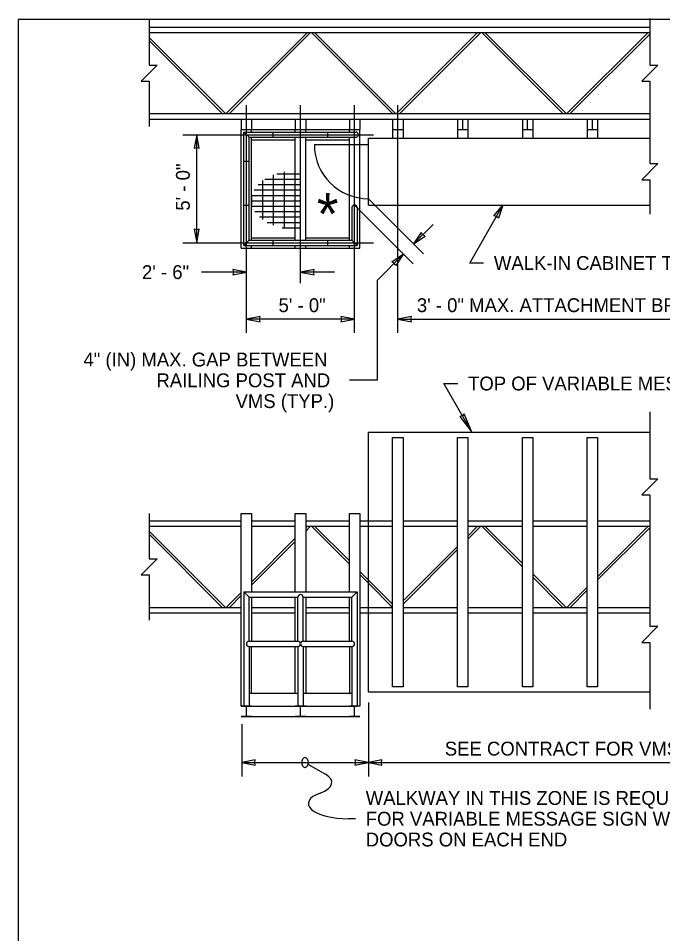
# Model space of a CAD drawing. Extents: x 99862 to 103151, y 100000 to 105076.
# Drawn here: x 99862 to 100607, y 101019 to 102077 of the extents above; entities that cross this region are included whole.
import ezdxf

# ---------------------------------------------------------------- set-up
doc = ezdxf.new("R2010")
doc.units = 0
for name, color, linetype in [('Level 1', 7, 'Continuous'), ('Level 14', 7, 'Continuous'), ('Level 15', 7, 'Continuous'), ('Level 18', 7, 'Continuous'), ('Level 2', 7, 'Continuous'), ('Level 20', 7, 'Continuous'), ('Level 22', 7, 'Continuous'), ('Level 23', 7, 'Continuous'), ('Level 26', 7, 'Continuous'), ('Level 27', 7, 'Continuous'), ('Level 7', 7, 'Continuous')]:
    doc.layers.add(name, color=color, linetype=linetype)

msp = doc.modelspace()

# ---------------------------------------------------------------- linework, layer by layer
at = {"layer": 'Level 1'}
msp.add_lwpolyline([(99862, 99999.5), (103151, 99999.5), (103151, 102075.5), (99862, 102075.5)], close=True, dxfattribs=at)
at = {"layer": 'Level 14'}
msp.add_line((100251.7, 101152), (100243.7, 101152), dxfattribs=at)
for centre, start_param, end_param in [((100178.1, 101194), 5.497747, 6.859209), ((100243.7, 101169.4), 2.356226, 4.712389)]:
    msp.add_ellipse(centre, major_axis=(46.4, 0), ratio=0.375, start_param=start_param, end_param=end_param, dxfattribs=at)
at = {"layer": 'Level 15'}
for p, q in [((100125.8, 101713.3), (100125.8, 101976.3)), ((100188.3, 101770.8), (100188.3, 101976.3)), ((100250.8, 101713.3), (100250.8, 101976.3)), ((100300.8, 101713.3), (100300.8, 101976.3)), ((100052.3, 101942.3), (100272.8, 101942.3)), ((100068.3, 101817.4), (100068.3, 101942.3)), ((100250.8, 101861), (100318.6, 101793.1)), ((100266.8, 101868.3), (100330.3, 101804.8)), ((100383.9, 101794), (100422.4, 101860.8)), ((100341.6, 101838.7), (100319, 101816.1)), ((100052.3, 101817.4), (100272.8, 101817.4)), ((100307.3, 101804.5), (100276.8, 101773.9)), ((100399.9, 101794), (100383.9, 101794)), ((100125.8, 101783.5), (100073.7, 101783.5)), ((100227.7, 101783.5), (100188.3, 101783.5)), ((100276.8, 101773.9), (100276.8, 101658.5)), ((100250.8, 101729.3), (100125.8, 101729.3)), ((100300.8, 101729.3), (100832, 101729.3)), ((100276.8, 101658.5), (100244.8, 101658.5)), ((100386.5, 101598.5), (100354, 101654.8)), ((100354, 101654.8), (100370, 101654.8)), ((100266.8, 101286.2), (100266.8, 101201)), ((100120.3, 101261.4), (100120.3, 101201)), ((100120.3, 101217), (100266.8, 101217)), ((100266.8, 101217), (100866.3, 101217)), ((100196.8, 101215.1), (100217, 101203.5))]:
    msp.add_line(p, q, dxfattribs=at)
for points in [[(100013.3, 102075), (100013.3, 102022.7), (100022.5, 102022.7), (100004, 102004.2), (100013.3, 102004.2), (100013.3, 101951.9)], [(100592.1, 102076.7), (100592.1, 102022.7), (100601.3, 102022.7), (100582.8, 102004.2), (100592.1, 102004.2), (100592.1, 101951.9)], [(100592.1, 101961.1), (100592.1, 101908.9), (100601.3, 101908.9), (100582.8, 101890.3), (100592.1, 101890.3), (100592.1, 101850.3)], [(100592.1, 101622.1), (100592.1, 101544.8), (100601.3, 101544.8), (100582.8, 101526.3), (100592.1, 101526.3), (100592.1, 101374.4), (100601.3, 101374.4), (100582.8, 101355.8), (100592.1, 101355.8), (100592.1, 101278.6)], [(100013.3, 101504.6), (100013.3, 101452.3), (100022.5, 101452.3), (100004, 101433.8), (100013.3, 101433.8), (100013.3, 101381.5)], [(100013.3, 101504.6), (100013.3, 101452.4), (100022.5, 101452.4), (100004, 101433.8), (100013.3, 101433.8), (100013.3, 101381.5)]]:
    msp.add_lwpolyline(points, dxfattribs=at)
for points in [[(100068.3, 101942.3), (100065.2, 101926.6), (100068.3, 101927.3), (100071.3, 101926.6)], [(100422.4, 101860.8), (100417.2, 101845.7), (100414.9, 101847.8), (100411.9, 101848.7)], [(100068.3, 101817.4), (100071.3, 101833.1), (100068.3, 101832.4), (100065.2, 101833.1)], [(100319, 101816.1), (100332.3, 101825), (100329.6, 101826.7), (100327.9, 101829.4)], [(100307.3, 101804.5), (100298.4, 101791.2), (100296.7, 101793.9), (100294, 101795.5)], [(100125.8, 101783.5), (100110, 101786.5), (100110.8, 101783.5), (100110, 101780.4)], [(100188.3, 101783.5), (100204, 101780.4), (100203.3, 101783.5), (100204, 101786.5)], [(100125.8, 101729.3), (100141.5, 101726.2), (100140.7, 101729.3), (100141.5, 101732.4)], [(100250.8, 101729.3), (100235, 101732.4), (100235.8, 101729.3), (100235, 101726.2)], [(100300.8, 101729.3), (100316.5, 101726.2), (100315.8, 101729.3), (100316.5, 101732.4)], [(100386.5, 101598.5), (100377.6, 101619.8), (100375.6, 101617.4), (100372.5, 101616.8)], [(100120.3, 101217), (100136, 101213.9), (100135.3, 101217), (100136, 101220.1)], [(100266.8, 101217), (100251, 101220.1), (100251.8, 101217), (100251, 101213.9)], [(100266.8, 101217), (100282.5, 101213.9), (100281.8, 101217), (100282.5, 101220.1)]]:
    msp.add_lwpolyline(points, close=True, dxfattribs=at)
msp.add_ellipse((100193.5, 101217), major_axis=(0, 6), ratio=0.57735, dxfattribs=at)
at = {"layer": 'Level 18'}
for p, q in [((100119.8, 101960.3), (100119.8, 101948.3)), ((100131.8, 101960.3), (100131.8, 101948.3)), ((100182.3, 101960.3), (100182.3, 101948.3)), ((100194.3, 101960.3), (100194.3, 101948.3)), ((100244.8, 101960.3), (100244.8, 101948.3)), ((100256.8, 101960.3), (100256.8, 101948.3))]:
    msp.add_line(p, q, dxfattribs=at)
at = {"layer": 'Level 2'}
for p, q in [((100119.8, 101960.3), (100131.8, 101960.3)), ((100294.8, 101960.3), (100294.8, 101938.3)), ((100306.8, 101960.3), (100306.8, 101938.3)), ((100369.8, 101960.3), (100369.8, 101938.3)), ((100381.8, 101960.3), (100381.8, 101938.3)), ((100444.8, 101960.3), (100444.8, 101938.3)), ((100456.8, 101960.3), (100456.8, 101938.3)), ((100519.8, 101960.3), (100519.8, 101938.3)), ((100531.8, 101960.3), (100531.8, 101938.3)), ((100119.8, 101948.3), (100131.8, 101948.3)), ((100119.8, 101948.3), (100256.8, 101948.3)), ((100119.8, 101811.3), (100119.8, 101948.3)), ((100131.8, 101945.3), (100131.8, 101948.3)), ((100182.3, 101945.3), (100182.3, 101948.3)), ((100194.3, 101945.3), (100194.3, 101948.3)), ((100244.8, 101945.3), (100244.8, 101948.3)), ((100256.8, 101811.3), (100256.8, 101948.3)), ((100122.8, 101814.4), (100122.8, 101945.3)), ((100122.8, 101945.3), (100252.2, 101945.3)), ((100122.8, 101945.3), (100128.8, 101939.3)), ((100128.8, 101939.3), (100252.2, 101939.3)), ((100128.8, 101820.4), (100128.8, 101939.3)), ((100131.8, 101820.4), (100131.8, 101939.3)), ((100131.8, 101936.3), (100182.3, 101936.3)), ((100156.8, 101939.3), (100156.8, 101945.3)), ((100182.3, 101820.4), (100182.3, 101939.3)), ((100194.3, 101820.4), (100194.3, 101939.3)), ((100194.3, 101936.3), (100244.8, 101936.3)), ((100219.8, 101939.3), (100219.8, 101945.3)), ((100244.8, 101820.4), (100244.8, 101939.3)), ((100266.8, 101860.8), (100266.8, 101938.3)), ((100266.8, 101938.3), (100592.1, 101938.3)), ((100204.3, 101930.8), (100266.8, 101930.8)), ((100128.8, 101911.3), (100122.8, 101911.3)), ((100128.8, 101860.4), (100122.8, 101860.4)), ((100247.8, 101858), (100247.8, 101820.4)), ((100253.8, 101858), (100253.8, 101814.4)), ((100266.8, 101860.8), (100592.1, 101860.8)), ((100122.8, 101814.4), (100128.8, 101820.4)), ((100128.8, 101820.4), (100247.8, 101820.4)), ((100131.8, 101823.3), (100182.3, 101823.3)), ((100156.8, 101814.4), (100156.8, 101820.4)), ((100194.3, 101823.3), (100244.8, 101823.3)), ((100219.8, 101814.4), (100219.8, 101820.4)), ((100247.8, 101820.4), (100253.8, 101814.4)), ((100119.8, 101811.3), (100256.8, 101811.3)), ((100122.8, 101814.4), (100253.8, 101814.4)), ((100131.8, 101811.3), (100131.8, 101814.4)), ((100182.3, 101811.3), (100182.3, 101814.4)), ((100194.3, 101811.3), (100194.3, 101814.4)), ((100244.8, 101811.3), (100244.8, 101814.4)), ((100266.8, 101298.5), (100266.8, 101598.5)), ((100266.8, 101598.5), (100592.1, 101598.5)), ((100122.8, 101414), (100128.8, 101408)), ((100247.8, 101408), (100253.8, 101414)), ((100266.8, 101298.5), (100592.1, 101298.5))]:
    msp.add_line(p, q, dxfattribs=at)
for points in [[(100294.8, 101592.5), (100306.8, 101592.5), (100306.8, 101304.5), (100294.8, 101304.5)], [(100369.8, 101592.5), (100381.8, 101592.5), (100381.8, 101304.5), (100369.8, 101304.5)], [(100444.8, 101592.5), (100456.8, 101592.5), (100456.8, 101304.5), (100444.8, 101304.5)], [(100519.8, 101592.5), (100531.8, 101592.5), (100531.8, 101304.5), (100519.8, 101304.5)]]:
    msp.add_lwpolyline(points, close=True, dxfattribs=at)
for centre, radius, start, end in [((100252.2, 101942.3), 3, 270, 90), ((100266.8, 101930.8), 62.5, 180, 270), ((100250.8, 101858), 3, 0, 180), ((100188.3, 101408), 3, 0, 180), ((100128.8, 101354), 3, 90, 270), ((100185.3, 101354), 3, 270, 90), ((100191.3, 101354), 3, 90, 270), ((100247.8, 101354), 3, 270, 90)]:
    msp.add_arc(centre, radius, start, end, dxfattribs=at)
at = {"layer": 'Level 22'}
for points in [[(100131.8, 101282), (100131.8, 101282), (100119.8, 101282), (100119.8, 101504.5), (100131.8, 101504.5), (100131.8, 101414)], [(100182.3, 101414), (100182.3, 101504.5), (100194.3, 101504.5), (100194.3, 101414)], [(100244.8, 101414), (100244.8, 101504.5), (100256.8, 101504.5), (100256.8, 101282), (100244.8, 101282), (100244.8, 101282)], [(100131.8, 101408), (100131.8, 101357)], [(100182.3, 101357), (100182.3, 101408)], [(100194.3, 101408), (100194.3, 101357)], [(100244.8, 101357), (100244.8, 101408)], [(100131.8, 101297), (100131.8, 101351)], [(100182.3, 101297), (100182.3, 101351)], [(100194.3, 101351), (100194.3, 101297)], [(100244.8, 101351), (100244.8, 101297)]]:
    msp.add_lwpolyline(points, dxfattribs=at)
at = {"layer": 'Level 23'}
for p, q in [((100119.8, 101960.3), (100131.8, 101960.3)), ((100125.8, 101948.3), (100125.8, 101960.3)), ((100182.3, 101960.3), (100194.3, 101960.3)), ((100188.3, 101948.3), (100188.3, 101960.3)), ((100244.8, 101960.3), (100256.8, 101960.3)), ((100250.8, 101948.3), (100250.8, 101960.3)), ((100294.8, 101960.3), (100306.8, 101960.3)), ((100300.8, 101948.3), (100300.8, 101960.3)), ((100369.8, 101960.3), (100381.8, 101960.3)), ((100375.8, 101948.3), (100375.8, 101960.3)), ((100444.8, 101960.3), (100456.8, 101960.3)), ((100450.8, 101948.3), (100450.8, 101960.3)), ((100519.8, 101960.3), (100531.8, 101960.3)), ((100525.8, 101948.3), (100525.8, 101960.3)), ((100119.8, 101948.3), (100131.8, 101948.3)), ((100182.3, 101948.3), (100194.3, 101948.3)), ((100244.8, 101948.3), (100256.8, 101948.3)), ((100294.8, 101948.3), (100306.8, 101948.3)), ((100369.8, 101948.3), (100381.8, 101948.3)), ((100444.8, 101948.3), (100456.8, 101948.3)), ((100519.8, 101948.3), (100531.8, 101948.3)), ((100131.8, 101282), (100119.8, 101282)), ((100125.8, 101270), (100125.8, 101282)), ((100194.3, 101282), (100182.3, 101282)), ((100188.3, 101270), (100188.3, 101282)), ((100256.8, 101282), (100244.8, 101282)), ((100250.8, 101270), (100250.8, 101282)), ((100131.8, 101270), (100119.8, 101270)), ((100194.3, 101270), (100182.3, 101270)), ((100256.8, 101270), (100244.8, 101270))]:
    msp.add_line(p, q, dxfattribs=at)
at = {"layer": 'Level 26'}
for p, q in [((100157.2, 101837.6), (100157.2, 101895.9)), ((100160.8, 101897.1), (100187.5, 101897.1)), ((100169.7, 101834.2), (100169.7, 101899.2)), ((100182.2, 101833.1), (100182.2, 101900.4)), ((100139.3, 101884.6), (100187.5, 101884.6)), ((100144.7, 101844.2), (100144.7, 101889.3)), ((100147, 101890.9), (100187.5, 101890.9)), ((100132.1, 101872.2), (100187.5, 101872.2)), ((100132.2, 101860.9), (100132.2, 101872.6)), ((100134.6, 101878.4), (100187.5, 101878.4)), ((100131.4, 101865.9), (100187.5, 101865.9)), ((100132.5, 101859.7), (100187.5, 101859.7)), ((100135.6, 101853.4), (100187.5, 101853.4)), ((100140.9, 101847.2), (100187.5, 101847.2)), ((100149.7, 101841), (100187.5, 101841)), ((100167, 101834.7), (100187.5, 101834.7))]:
    msp.add_line(p, q, dxfattribs=at)
at = {"layer": 'Level 27'}
for p, q in [((100122.8, 101414), (100253.8, 101414)), ((100122.8, 101414), (100122.8, 101282)), ((100128.8, 101408), (100185.3, 101408)), ((100128.8, 101357), (100128.8, 101408)), ((100185.3, 101357), (100185.3, 101408)), ((100191.3, 101408), (100247.8, 101408)), ((100191.3, 101357), (100191.3, 101408)), ((100247.8, 101357), (100247.8, 101408)), ((100253.8, 101414), (100253.8, 101282)), ((100128.8, 101357), (100185.3, 101357)), ((100191.3, 101357), (100247.8, 101357)), ((100128.8, 101351), (100185.3, 101351)), ((100128.8, 101351), (100128.8, 101282)), ((100185.3, 101351), (100185.3, 101282)), ((100191.3, 101351), (100247.8, 101351)), ((100191.3, 101351), (100191.3, 101282)), ((100247.8, 101351), (100247.8, 101282)), ((100128.8, 101297), (100185.3, 101297)), ((100191.3, 101297), (100247.2, 101297)), ((100119.8, 101282), (100253.2, 101282)), ((100119.8, 101270), (100256.8, 101270))]:
    msp.add_line(p, q, dxfattribs=at)
at = {"layer": 'Level 7'}
for p, q in [((100013.3, 102066.6), (100592.1, 102066.6)), ((100013.3, 102060.3), (100592.1, 102060.3)), ((100013.3, 102054.7), (100101.4, 101966.6)), ((100196.2, 102060.3), (100102.4, 101966.6)), ((100199.9, 102060.3), (100106.1, 101966.6)), ((100200.9, 102060.3), (100294.7, 101966.6)), ((100204.6, 102060.3), (100298.3, 101966.6)), ((100393.1, 102060.3), (100299.4, 101966.6)), ((100396.8, 102060.3), (100303.1, 101966.6)), ((100397.9, 102060.3), (100491.6, 101966.6)), ((100401.5, 102060.3), (100495.3, 101966.6)), ((100590.1, 102060.3), (100496.3, 101966.6)), ((100592.1, 102058.6), (100500, 101966.6)), ((100013.3, 102051), (100097.7, 101966.6)), ((100013.3, 101966.6), (100592.1, 101966.6)), ((100013.3, 101960.3), (100592.1, 101960.3)), ((100013.3, 101496.2), (100119.8, 101496.2)), ((100131.8, 101496.2), (100182.3, 101496.2)), ((100194.3, 101496.2), (100244.8, 101496.2)), ((100256.8, 101496.2), (100266.8, 101496.2)), ((100266.8, 101496.2), (100294.8, 101496.2)), ((100306.8, 101496.2), (100369.8, 101496.2)), ((100381.8, 101496.2), (100444.8, 101496.2)), ((100456.8, 101496.2), (100519.8, 101496.2)), ((100531.8, 101496.2), (100592.1, 101496.2)), ((100013.3, 101490), (100119.8, 101490)), ((100013.3, 101484.4), (100101.4, 101396.2)), ((100013.3, 101480.7), (100097.7, 101396.2)), ((100131.8, 101490), (100182.3, 101490)), ((100199.9, 101490), (100194.3, 101484.3)), ((100196.2, 101490), (100194.3, 101488)), ((100194.3, 101490), (100244.8, 101490)), ((100200.9, 101490), (100244.8, 101446.1)), ((100204.6, 101490), (100244.8, 101449.8)), ((100256.8, 101490), (100266.8, 101490)), ((100266.8, 101490), (100294.8, 101490)), ((100306.8, 101490), (100369.8, 101490)), ((100396.8, 101490), (100381.8, 101474.9)), ((100393.1, 101490), (100381.8, 101478.6)), ((100381.8, 101490), (100444.8, 101490)), ((100397.9, 101490), (100444.8, 101443.1)), ((100401.5, 101490), (100444.8, 101446.8)), ((100456.8, 101490), (100519.8, 101490)), ((100590.1, 101490), (100531.8, 101431.6)), ((100531.8, 101490), (100592.1, 101490)), ((100592.1, 101488.2), (100531.8, 101427.9)), ((100182.3, 101476), (100131.8, 101425.5)), ((100182.3, 101472.3), (100131.8, 101421.8)), ((100369.8, 101466.6), (100306.8, 101403.6)), ((100369.8, 101462.9), (100306.8, 101399.9)), ((100256.8, 101437.8), (100266.8, 101427.8)), ((100256.8, 101434.1), (100266.8, 101424.1)), ((100266.8, 101427.8), (100294.8, 101399.8)), ((100456.8, 101434.8), (100495.3, 101396.2)), ((100456.8, 101431.1), (100491.6, 101396.2)), ((100266.8, 101424.1), (100294.7, 101396.2)), ((100519.8, 101419.6), (100496.3, 101396.2)), ((100119.8, 101413.5), (100102.4, 101396.2)), ((100119.8, 101409.8), (100106.1, 101396.2)), ((100519.8, 101415.9), (100500, 101396.2)), ((100013.3, 101396.2), (100119.8, 101396.2)), ((100131.8, 101396.2), (100182.3, 101396.2)), ((100194.3, 101396.2), (100244.8, 101396.2)), ((100256.8, 101396.2), (100266.8, 101396.2)), ((100266.8, 101396.2), (100294.8, 101396.2)), ((100306.8, 101396.2), (100369.8, 101396.2)), ((100381.8, 101396.2), (100444.8, 101396.2)), ((100456.8, 101396.2), (100519.8, 101396.2)), ((100531.8, 101396.2), (100592.1, 101396.2)), ((100013.3, 101390), (100119.8, 101390)), ((100131.8, 101390), (100182.3, 101390)), ((100194.3, 101390), (100244.8, 101390)), ((100256.8, 101390), (100266.8, 101390)), ((100266.8, 101390), (100294.8, 101390)), ((100306.8, 101390), (100369.8, 101390)), ((100381.8, 101390), (100444.8, 101390)), ((100456.8, 101390), (100519.8, 101390)), ((100531.8, 101390), (100592.1, 101390))]:
    msp.add_line(p, q, dxfattribs=at)

# ---------------------------------------------------------------- texts
at = {"layer": 'Level 20'}
msp.add_text('5\' - 0"', height=16, rotation=90, dxfattribs=at).set_placement((100060.3, 101854.5))
for s, height, p in [('*', 48, (100207.2, 101826.8)), ('WALK-IN CABINET TYPE VMS', 16, (100411.9, 101786)), ('2\' - 6"', 16, (100005, 101775.5)), ('5\' - 0"', 16, (100162.9, 101737.3)), ('3\' - 0" MAX. ATTACHMENT BRACKET SPACING', 16, (100322.8, 101737.3)), ('4" (IN) MAX. GAP BETWEEN', 16, (99937.3, 101674.5)), ('RAILING POST AND', 16, (100021.7, 101650.5)), ('TOP OF VARIABLE MESSAGE SIGN', 16, (100382, 101646.8)), ('VMS (TYP.)', 16, (100113.2, 101626.5)), ('SEE CONTRACT FOR VMS DIMENSIONS', 16, (100355.1, 101225)), ('WALKWAY IN THIS ZONE IS REQUIRED', 16, (100263.7, 101168)), ('FOR VARIABLE MESSAGE SIGN WITH', 16, (100263.7, 101144)), ('DOORS ON EACH END', 16, (100263.7, 101120))]:
    msp.add_text(s, height=height, dxfattribs=at).set_placement(p)

doc.saveas('drawing.dxf')
